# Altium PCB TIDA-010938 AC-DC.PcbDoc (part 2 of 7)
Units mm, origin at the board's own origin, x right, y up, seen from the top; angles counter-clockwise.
Board outline 275 x 170 mm, 4 copper layers (Top Layer, Layer 1, Layer 2, Bottom Layer), stack 1.787 mm thick; 711 components, 426 nets, 2196 pads, 1444 vias.
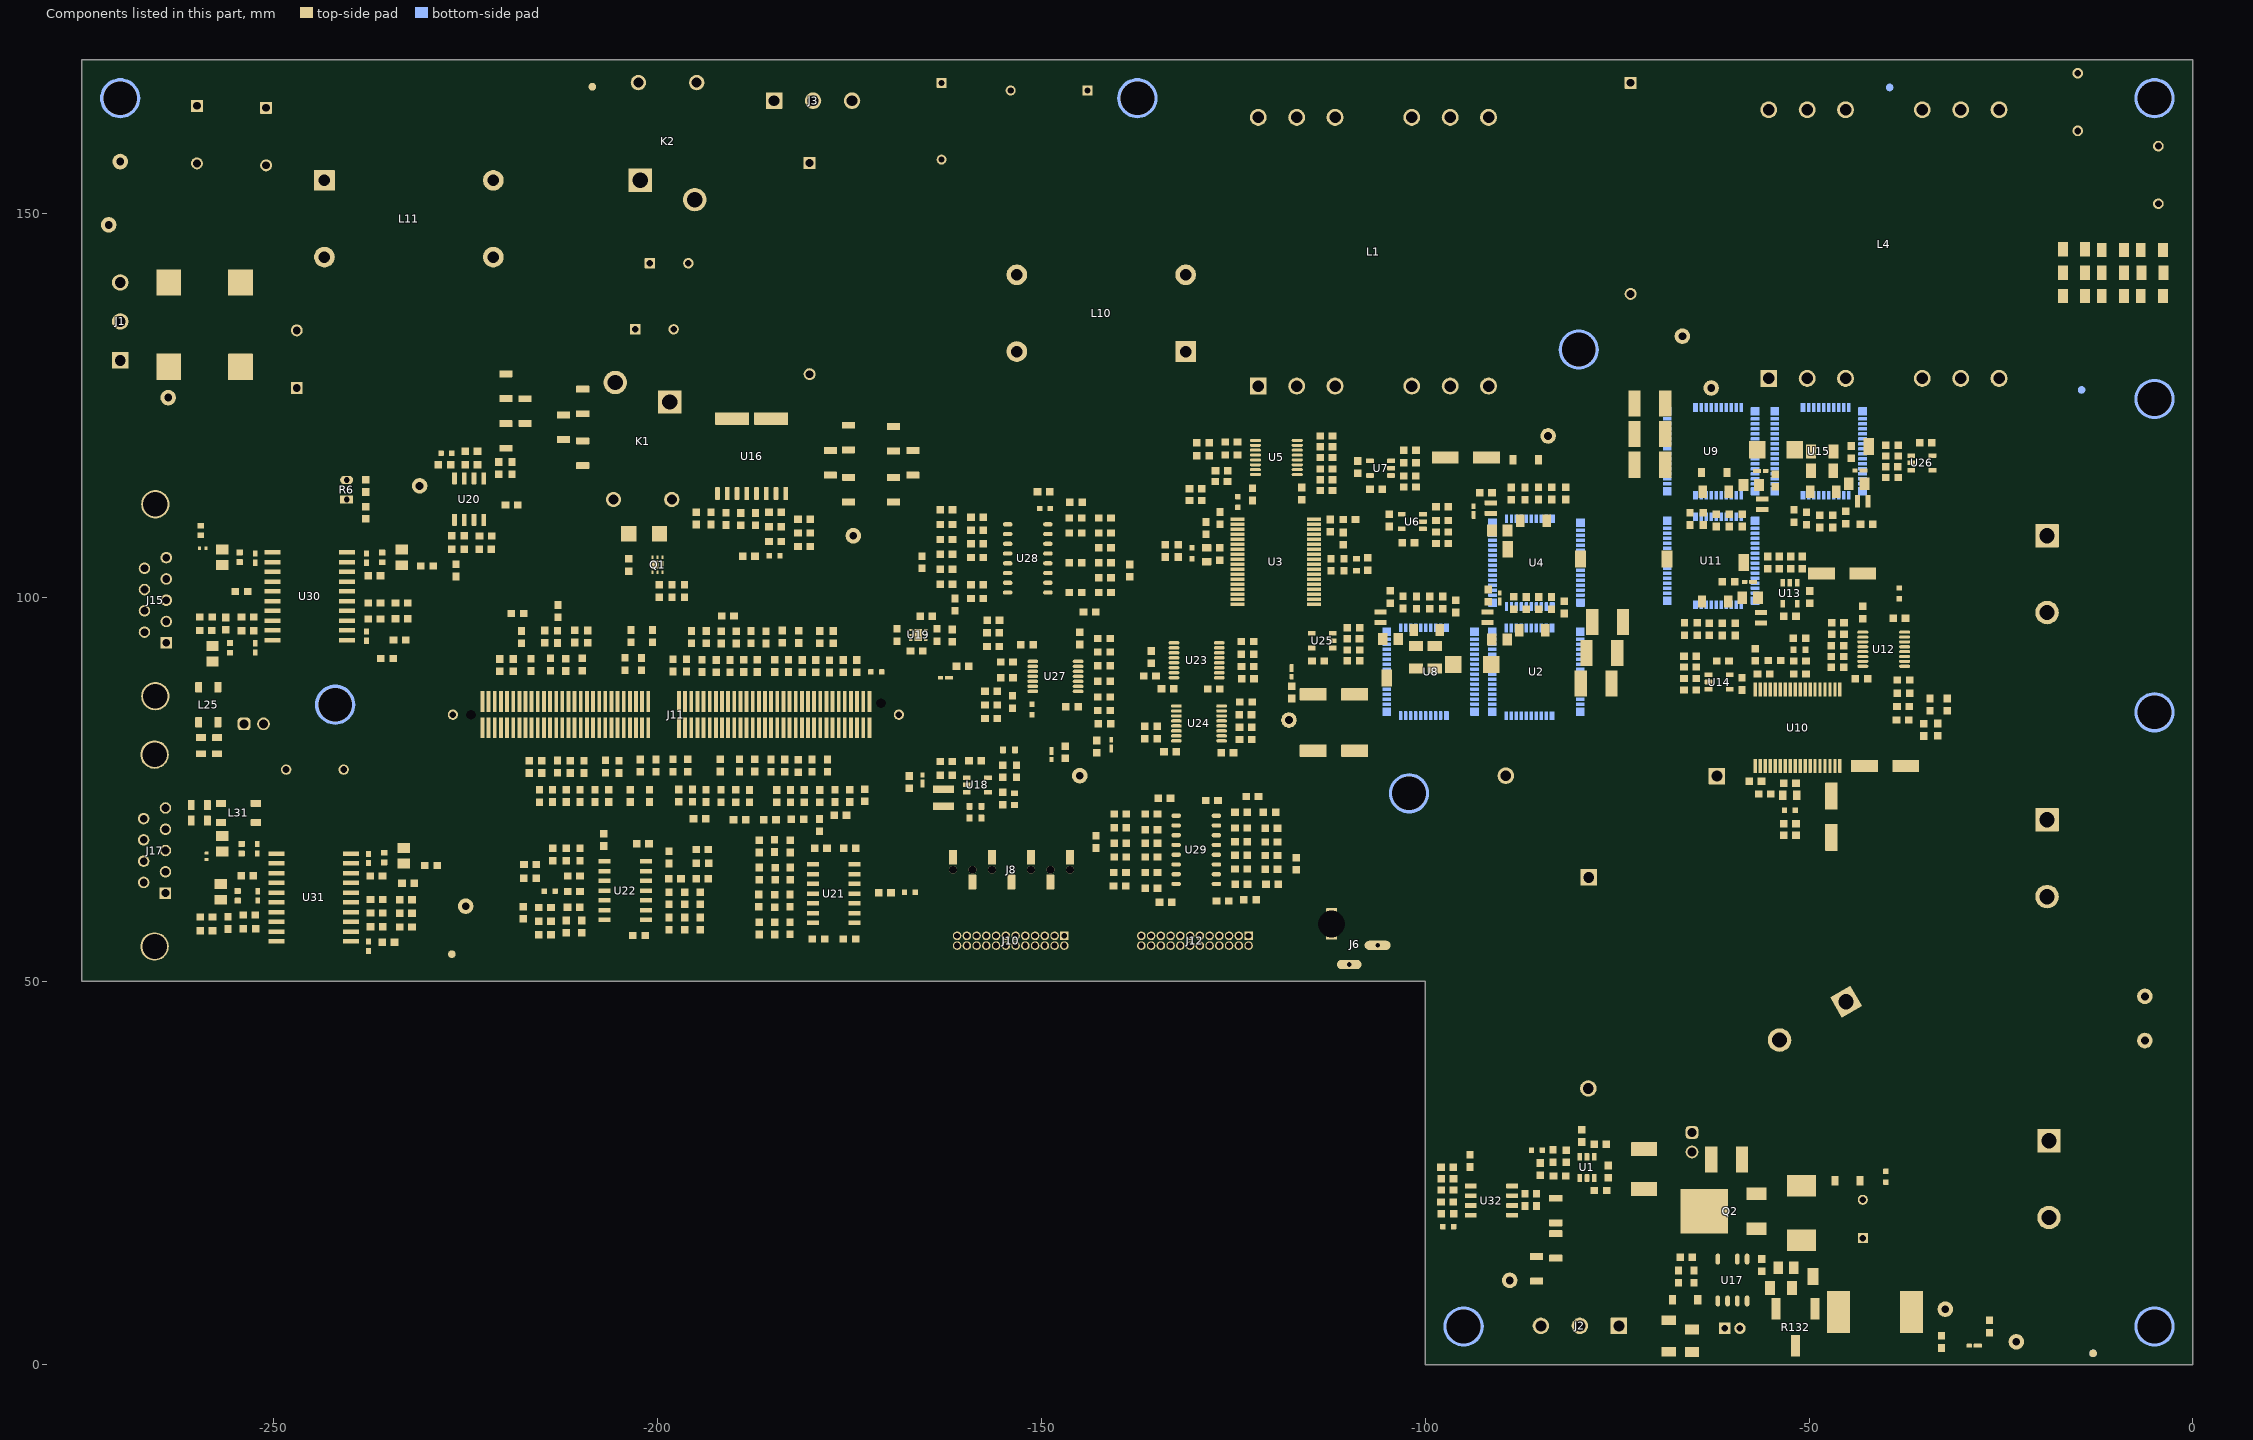
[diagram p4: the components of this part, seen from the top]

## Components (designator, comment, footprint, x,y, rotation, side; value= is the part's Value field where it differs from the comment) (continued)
R127 "TNPV12061M00BEEN" TNPV1206 -169.25,120.65 r270 top value=1.00Meg
R128 "TNPV12061M00BEEN" TNPV1206 -166.75,117.5 r270 top value=1.00Meg
R129 "TNPV12061M00BEEN" TNPV1206 -169.275,114 r270 top value=1.00Meg
R130 "RG1608P-103-B-T5" 0603 -224.25,117.25 r0 top value=10.0k
R131 "RG1608P-103-B-T5" 0603 -226,108 r0 top value=10.0k
R132 "3269W-1-104LF" FP-3269W-1-104LF_SMD-MFG -51.75,4.9 r180 top
R133 "RG1608P-103-B-T5" 0603 -97.15,25.75 r0 top value=10.0k
R134 "RG1608P-560-B-T5" 0603 -97.15,21.225 r180 top value=56
R135 "RG1608P-103-B-T5" 0603 -97.125,24.25 r180 top value=10.0k
R136 "RT0603BRD077K32L" 0603 -216.625,63.4 r180 top value=7.32k
R139 "RT0603BRD077K32L" 0603 -216.597,65.173 r0 top value=7.32k
R140 "RG1608P-560-B-T5" 0603 -175.001,55.474 r180 top value=56
R141 "RG1608P-560-B-T5" 0603 -206.998,68.379 r90 top value=56
R143 "RT0603BRD077K32L" 0603 -213.657,66.476 r270 top value=7.32k
R145 "RT0603BRD077K32L" 0603 -211.879,66.476 r270 top value=7.32k
R147 "RG1608P-103-B-T5" 0603 -214.673,59.576 r180 top value=10.0k
R149 "RG1608P-103-B-T5" 0603 -217.5,58.894 r270 top value=10.0k
R150 "RG1608P-560-B-T5" 0603 -174.968,67.302 r180 top value=56
R151 "RG1608P-560-B-T5" 0603 -214.673,56.02 r180 top value=56
R153 "RG1608P-103-B-T5" 0603 -214.673,57.798 r180 top value=10.0k
R155 "RG1608P-103-B-T5" 0603 -211.912,57.078 r270 top value=10.0k
R156 "RT0603BRD077K32L" 0603 -196.467,60.78 r90 top value=7.32k
R157 "RG1608P-103-B-T5" 0603 -184.675,63.975 r270 top value=10.0k
R158 "RG1608P-103-B-T5" 0603 -186.769,63.981 r90 top value=10.0k
R159 "RT0603BRD077K32L" 0603 -194.435,60.78 r270 top value=7.32k
R160 "RG1608P-560-B-T5" 0603 -178.74,67.3 r0 top value=56
R161 "RG1608P-560-B-T5" 0603 -202.426,55.933 r180 top value=56
R162 "RG1608P-103-B-T5" 0603 -186.769,67.537 r90 top value=10.0k
R163 "RT0603BRD077K32L" 0603 -194.435,57.478 r90 top value=7.32k
R164 "RG1608P-103-B-T5" 0603 -184.775,67.6 r90 top value=10.0k
R165 "RT0603BRD077K32L" 0603 -196.467,57.478 r90 top value=7.32k
R166 "RG1608P-103-B-T5" 0603 -194.143,65.352 r180 top value=10.0k
R167 "RG1608P-103-B-T5" 0603 -184.725,60.425 r270 top value=10.0k
R168 "RG1608P-103-B-T5" 0603 -186.802,60.467 r90 top value=10.0k
R169 "RG1608P-560-B-T5" 0603 -179.032,55.472 r0 top value=56
R170 "RG1608P-560-B-T5" 0603 -198.499,66.114 r90 top value=56
R171 "RG1608P-103-B-T5" 0603 -186.769,56.869 r270 top value=10.0k
R172 "RG1608P-103-B-T5" 0603 -194.181,63.32 r0 top value=10.0k
R173 "RG1608P-103-B-T5" 0603 -184.737,56.869 r270 top value=10.0k
R174 "RCS06030000Z0EA" 0603 -218.787,91.139 r90 top value=0
R175 "RCS06030000Z0EA" 0603 -217.738,94.798 r90 top value=0
R176 "RCS06030000Z0EA" 0603 -210.8,94.9 r270 top value=0
R177 "RCS06030000Z0EA" 0603 -123.15,94.225 r180 top value=0
R178 "RCS06030000Z0EA" 0603 -211.975,91.175 r270 top value=0
R179 "RCS06030000Z0EA" 0603 -216.501,91.177 r90 top value=0
R180 "RCS06030000Z0EA" 0603 -213.025,94.825 r270 top value=0
R181 "RCS06030000Z0EA" 0603 -213.95,91.225 r270 top value=0
R182 "RCS06030000Z0EA" 0603 -215.375,74.1 r270 top value=0
R183 "RCS06030000Z0EA" 0603 -215.075,77.9 r270 top value=0
R184 "RCS06030000Z0EA" 0603 -213.025,77.925 r270 top value=0
R185 "ERJ-8ENF1693V" 1206 -10.423,145.226 r0 top value=169k
R186 "RCS06030000Z0EA" 0603 -210.118,74.129 r90 top value=0
R187 "RCS06030000Z0EA" 0603 -209.585,77.901 r90 top value=0
R188 "RCS06030000Z0EA" 0603 -208.153,74.116 r90 top value=0
R189 "RCS06030000Z0EA" 0603 -206.791,77.939 r90 top value=0
R190 "RCS06030000Z0EA" 0603 -203.55,74.125 r90 top value=0
R191 "RCS06030000Z0EA" 0603 -202.1,91.275 r90 top value=0
R192 "RCS06030000Z0EA" 0603 -202.244,78.051 r90 top value=0
R193 "RCS06030000Z0EA" 0603 -200.65,94.925 r90 top value=0
R194 "RCS06030000Z0EA" 0603 -204.25,91.3 r270 top value=0
R195 "RCS06030000Z0EA" 0603 -196.05,78.075 r270 top value=0
R196 "RCS06030000Z0EA" 0603 -203.45,94.925 r270 top value=0
R197 "RCS06030000Z0EA" 0603 -195.45,74.15 r270 top value=0
R198 "RCS06030000Z0EA" 0603 -201.05,74.125 r90 top value=0
R199 "RCS06030000Z0EA" 0603 -200.2,78.05 r90 top value=0
R200 "RCS06030000Z0EA" 0603 -198,78.075 r90 top value=0
R201 "RCS06030000Z0EA" 0603 -197.225,74.15 r90 top value=0
R202 "RCS06030000Z0EA" 0603 -123.35,86.35 r180 top value=0
R203 "RCS06030000Z0EA" 0603 -193.69,74.125 r90 top value=0
R204 "RCS06030000Z0EA" 0603 -196.219,91.126 r90 top value=0
R205 "RCS06030000Z0EA" 0603 -191.83,78.089 r90 top value=0
R206 "RCS06030000Z0EA" 0603 -193.641,94.798 r90 top value=0
R207 "RCS06030000Z0EA" 0603 -192.338,91.026 r90 top value=0
R208 "RCS06030000Z0EA" 0603 -191.699,94.776 r90 top value=0
R209 "RCS06030000Z0EA" 0603 -190.56,91.026 r90 top value=0
R210 "RCS06030000Z0EA" 0603 -189.325,78.1 r90 top value=0
R211 "RCS06030000Z0EA" 0603 -189.758,94.776 r90 top value=0
R212 "RCS06030000Z0EA" 0603 -188.02,74.091 r90 top value=0
R213 "RCS06030000Z0EA" 0603 -188.782,91.064 r90 top value=0
R214 "RCS06030000Z0EA" 0603 -187.325,78.1 r90 top value=0
R215 "RCS06030000Z0EA" 0603 -187.816,94.798 r90 top value=0
R216 "RCS06030000Z0EA" 0603 -187.004,91.064 r90 top value=0
R217 "RCS06030000Z0EA" 0603 -185.226,78.051 r90 top value=0
R218 "RCS06030000Z0EA" 0603 -185.875,94.775 r90 top value=0
R219 "RCS06030000Z0EA" 0603 -184.464,74.091 r90 top value=0
R220 "RCS06030000Z0EA" 0603 -184.718,91.064 r90 top value=0
R221 "RCS06030000Z0EA" 0603 -183.448,78.051 r90 top value=0
R222 "RCS06030000Z0EA" 0603 -183.75,94.85 r90 top value=0
R223 "RCS06030000Z0EA" 0603 -182.686,74.091 r90 top value=0
R224 "RCS06030000Z0EA" 0603 -182.94,91.064 r90 top value=0
R225 "RCS06030000Z0EA" 0603 -181.67,78.013 r90 top value=0
R226 "RCS06030000Z0EA" 0603 -181.609,94.825 r90 top value=0
R227 "RCS06030000Z0EA" 0603 -180.908,74.091 r90 top value=0
R228 "RCS06030000Z0EA" 0603 -181.162,91.026 r90 top value=0
R229 "RCS06030000Z0EA" 0603 -179.892,78.051 r90 top value=0
R230 "RCS06030000Z0EA" 0603 -179.384,91.026 r90 top value=0
R231 "RCS06030000Z0EA" 0603 -178.876,74.091 r90 top value=0
R232 "RCS06030000Z0EA" 0603 -178.876,94.798 r90 top value=0
R233 "RCS06030000Z0EA" 0603 -177.86,78.051 r90 top value=0
R234 "RCS06030000Z0EA" 0603 -177.606,90.988 r90 top value=0
R235 "ERJ-8ENF1693V" 1206 -10.423,142.273 r0 top value=169k
R236 "RCS06030000Z0EA" 0603 -177.098,94.798 r90 top value=0
R237 "RG1608P-103-B-T5" 0603 -97.8,107 r180 top value=10.0k
R238 "RG1608P-560-B-T5" 0603 -156.541,84.189 r0 top value=56
R239 "RG1608P-560-B-T5" 0603 -154.509,89.523 r180 top value=56
R240 "RCS06030000Z0EA" 0603 -122.525,74.025 r180 top value=0
R241 "RCS06030000Z0EA" 0603 -145.5,112.375 r180 top value=0
R242 "RCS06030000Z0EA" 0603 -116.8,65.275 r270 top value=0
R243 "RCS06030000Z0EA" 0603 -138.475,103.45 r270 top value=0
R244 "RCS06030000Z0EA" 0603 -122.827,60.598 r180 top value=0
R245 "RCS06030000Z0EA" 0603 -143.725,98.075 r180 top value=0
R246 "RCS06030000Z0EA" 0603 -133.825,60.25 r180 top value=0
R247 "RCS06030000Z0EA" 0603 -161.25,99.025 r270 top value=0
R248 "RCS06030000Z0EA" 0603 -142.9,68.125 r270 top value=0
R249 "RCS06030000Z0EA" 0603 -165.55,104.55 r270 top value=0
R250 "RCS06030000Z0EA" 0603 -133.975,73.825 r0 top value=0
R251 "RCS06030000Z0EA" 0603 -158.375,110.425 r180 top value=0
R252 "RG1608P-103-B-T5" 0603 -141.846,87.008 r180 top value=10.0k
R253 "RG1608P-103-B-T5" 0603 -123.983,72.001 r180 top value=10.0k
R254 "RG1608P-103-B-T5" 0603 -145.553,110.312 r180 top value=10.0k
R255 "RG1608P-103-B-T5" 0603 -141.846,91.072 r180 top value=10.0k
R256 "RG1608P-103-B-T5" 0603 -154.509,91.555 r0 top value=10.0k
R257 "RG1608P-560-B-T5" 0603 -158.375,106.947 r180 top value=56
R258 "RG1608P-103-B-T5" 0603 -156.541,87.745 r0 top value=10.0k
R259 "RG1608P-560-B-T5" 0603 -135.667,69.715 r180 top value=56
R260 "RG1608P-560-B-T5" 0603 -162.385,109.463 r0 top value=56
R263 "RG1608P-560-B-T5" 0603 -139.731,71.747 r0 top value=56
R264 "RG1608P-560-B-T5" 0603 -135.667,66.159 r180 top value=56
R265 "RG1608P-560-B-T5" 0603 -162.385,105.58 r0 top value=56
R267 "RG1608P-560-B-T5" 0603 -139.731,67.937 r0 top value=56
R268 "RG1608P-560-B-T5" 0603 -162.385,101.697 r0 top value=56
R269 "RG1608P-560-B-T5" 0603 -158.375,99.835 r180 top value=56
R270 "RG1608P-560-B-T5" 0603 -139.769,64.127 r0 top value=56
R272 "RG1608P-560-B-T5" 0603 -135.667,62.095 r180 top value=56
R273 "RG1608P-560-B-T5" 0603 -141.743,100.602 r180 top value=56
R274 "RG1608P-560-B-T5" 0603 -119.935,62.603 r180 top value=56
R276 "RG1608P-560-B-T5" 0603 -141.743,104.485 r180 top value=56
R278 "RG1608P-560-B-T5" 0603 -120.049,66.344 r180 top value=56
R279 "RG1608P-560-B-T5" 0603 -126.4,60.425 r0 top value=56
R280 "RT0603DRE0759R7L" 0603 -253.41,95.645 r0 top value=59.7
R281 "RG1608P-560-B-T5" 0603 -141.743,108.368 r180 top value=56
R282 "RG1608P-560-B-T5" 0603 -120.049,69.9 r180 top value=56
R284 "RG1608P-560-B-T5" 0603 -123.983,64.602 r0 top value=56
R286 "RG1608P-560-B-T5" 0603 -123.983,68.158 r0 top value=56
R287 "RT0603DRE0759R7L" 0603 -253.41,97.423 r180 top value=59.7
R288 "RT0603DRE0759R7L" 0603 -253.152,56.82 r0 top value=59.7
R289 "RT0603DRE0759R7L" 0603 -253.19,58.598 r180 top value=59.7
R290 "ERJ-8ENF1693V" 1206 -10.423,139.225 r0 top value=169k
R291 "ERJ-8ENF1693V" 1206 -15.503,139.225 r0 top value=169k
R297 "RG1608P-103-B-T5" 0603 -141.743,110.31 r180 top value=10.0k
R298 "RG1608P-103-B-T5" 0603 -141.743,106.427 r180 top value=10.0k
R299 "RG1608P-103-B-T5" 0603 -141.743,102.544 r180 top value=10.0k
R300 "RG1608P-103-B-T5" 0603 -162.385,103.639 r0 top value=10.0k
R301 "RG1608P-103-B-T5" 0603 -162.385,107.522 r0 top value=10.0k
R302 "RG1608P-103-B-T5" 0603 -162.385,111.405 r0 top value=10.0k
R303 "RG1608P-103-B-T5" 0603 -120.289,72.001 r180 top value=10.0k
R304 "RG1608P-103-B-T5" 0603 -120.049,68.122 r180 top value=10.0k
R305 "RG1608P-103-B-T5" 0603 -120.049,64.566 r180 top value=10.0k
R306 "RG1608P-103-B-T5" 0603 -139.807,62.386 r0 top value=10.0k
R307 "RG1608P-103-B-T5" 0603 -139.731,66.159 r0 top value=10.0k
R308 "RG1608P-103-B-T5" 0603 -139.731,69.969 r0 top value=10.0k
R310 "RG1608P-103-B-T5" 0603 -236.9,102.794 r0 top value=10.0k
R311 "RG1608P-560-B-T5" 0603 -233.344,97.206 r180 top value=56
R312 "RMCF0805ZT0R00" FP-RMCF0805ZT0R00_0805-MFG -257.375,80.65 r270 top
R314 "RG1608P-560-B-T5" 0603 -233.344,99.238 r180 top value=56
R316 "RMCF0805ZT0R00" FP-RMCF0805ZT0R00_0805-MFG -259.475,80.65 r270 top
R318 "RG1608P-103-B-T5" 0603 -236.642,63.678 r0 top value=10.0k
R319 "RG1608P-560-B-T5" 0603 -236.604,58.852 r180 top value=56
R320 "RG1608P-560-B-T5" 0603 -236.604,60.63 r180 top value=56
R321 "RMCF0805ZT0R00" FP-RMCF0805ZT0R00_0805-MFG -259.7,70.9 r180 top
R323 "RG1608P-560-B-T5" 0603 -236.604,57.074 r180 top value=56
R325 "RMCF0805ZT0R00" FP-RMCF0805ZT0R00_0805-MFG -259.7,72.9 r180 top
R326 "ERJ-8ENF1693V" 1206 -15.503,145.321 r0 top value=169k
R327 "ERJ-8ENF1693V" 1206 -15.503,142.273 r0 top value=169k
R328 "RG1608P-103-B-T5" 0603 -97.8,111.8 r180 top value=10.0k
R329 "RG1608P-103-B-T5" 0603 -102,114.35 r180 top value=10.0k
R330 "RG1608P-103-B-T5" 0603 -102,119.125 r180 top value=10.0k
R331 "RG1608P-103-B-T5" 0603 -50.9,104.5 r270 top value=10.0k
R332 "RG1608P-103-B-T5" 0603 -55.4,104.5 r270 top value=10.0k
R335 "RG1608P-103-B-T5" 0603 -109.35,91.725 r180 top value=10.0k
R336 "RG1608P-103-B-T5" 0603 -39.2,119.8 r0 top value=10.0k
R337 "RG1608P-103-B-T5" 0603 -109.35,96.025 r180 top value=10.0k
R338 "RG1608P-103-B-T5" 0603 -39.2,115.6 r0 top value=10.0k
TP1 "S2751-46R" Harwin_S2751-46R -68.5,105 r90 top
TP2 "5001" Keystone5001 -225,59.75 r90 top
TP3 "5001" Keystone5001 -174.5,108 r90 top
TP4 "5001" Keystone5001 -84,121 r90 top
TP5 "S2751-46R" Harwin_S2751-46R -79.775,104.952 r90 top
TP6 "5001" Keystone5001 -231,114.5 r90 top
TP7 "5000" Keystone5000 -89,11 r90 top
TP8 "5001" Keystone5001 -6.25,42.25 r90 top
TP9 "5001" Keystone5001 -66.5,134 r90 top
TP10 "5001" Keystone5001 -62.75,127.25 r90 top
TP11 "S2751-46R" Harwin_S2751-46R -42.234,119.65 r90 top
TP12 "5001" Keystone5001 -117.75,84 r90 top
TP13 "5001" Keystone5001 -271.5,148.5 r90 top
TP14 "5116" Keystone_5116 -270,156.75 r0 top
TP15 "5117" Keystone5117 -263.75,126 r90 top
TP16 "S2751-46R" Harwin_S2751-46R -105.018,89.452 r90 top
TP17 "S2751-46R" Harwin_S2751-46R -89.25,106.25 r270 top
TP18 "S2751-46R" Harwin_S2751-46R -58.5,104.5 r90 top
TP19 "5000" Keystone5000 -6.25,48 r90 top
TP20 "5000" Keystone5000 -32.25,7.25 r90 top
TP21 "5001" Keystone5001 -23,3 r90 top
TP22 "5001" Keystone5001 -145,76.75 r90 top
TP23 "S2751-46R" Harwin_S2751-46R -49.5,11.5 r90 top
U1 "INA181A3IDBV" DBV0006A_N -78.933,25.718 r90 top
U2 "LMG3522R030-Q1" RQS0052C-C01-MFG -85.535,90.275 r180 bottom
U3 "UCC14131QDWNRQ1" DWJ0036A-MFG -119.475,104.625 r0 top
U4 "LMG3522R030-Q1" RQS0052C-C01-MFG -85.5,104.5 r180 bottom
U5 "ISO7762DBQR" DBQ0016A_N -119.4,118.2 r180 top
U6 "SN74LVC1G08DBVT" DBV0005A_N -101.675,109.85 r180 top
U7 "SN74LVC1G08DBVT" DBV0005A_N -105.825,116.8 r180 top
U8 "LMG3522R030-Q1" RQS0052C-C01-MFG -99.293,90.3 r180 bottom
U9 "LMG3522R030-Q1" RQS0052C-C01-MFG -62.75,119 r0 bottom
U10 "UCC14131QDWNRQ1" DWJ0036A-MFG -51.5,83 r90 top
U11 "LMG3522R030-Q1" RQS0052C-C01-MFG -62.75,104.75 r0 bottom
U12 "ISO7762DBQR" DBQ0016A_N -40.275,93.223 r0 top
U13 "SN74LVC1G08DBVT" DBV0005A_N -52.5,100.5 r270 top
U14 "SN74LVC1G08DBVT" DBV0005A_N -61.725,88.95 r0 top
U15 "LMG3522R030-Q1" RQS0052C-C01-MFG -48.75,119 r0 bottom
U16 "TMCS1123B2QDVGR" DVG0010A-MFG -187.75,118.391 r270 top
U17 "UCC28710DR" D0007A_N -59.984,11.052 r90 top
U18 "TPS560200DBVR" DBV0005A_N -158.333,75.549 r0 top
U19 "TLV75533PDRVR" DRV0006A -166.06,95.076 r0 top
U20 "OPA2388IDR" D0008A-MFG -224.55,112.775 r90 top
U21 "OPA4388IDR" D0014A-MFG -177.047,61.387 r180 top
U22 "OPA4388IDR" D0014A-MFG -204.204,61.775 r0 top
U23 "SN74HC251PW" PW0016A_N -129.775,91.775 r180 top
U24 "SN74HC251PW" PW0016A_N -129.475,83.55 r180 top
U25 "SN74LVC1G08DBVT" DBV0005A_N -113.426,94.329 r180 top
U26 "SN74LVC1G08DBVT" DBV0005A_N -35.3,117.5 r0 top
U27 "SN74LVC126APWR" PW0014A_N -148.169,89.683 r180 top
U28 "SN74HC365D" D0016A_L -151.775,105.05 r0 top
U29 "SN74HC365D" D0016A_L -129.825,67.09 r0 top
U30 "ISOW1044DFM" DFM0020A-MFG -245.306,100.127 r180 top
U31 "ISOW1412DFM" DFM0020A-MFG -244.77,60.884 r180 top
U32 "OPA2388IDR" D0008A-MFG -91.375,21.4 r180 top
ZZ1 "This Assembly Note is for PCB labels only" AssemblyNoteLabel -281.335,-76 r0 top
ZZ2 "These assemblies are ESD sensitive, ESD precautions shall be observed." AssemblyNote -218.585,-72.25 r0 top
ZZ3 "These assemblies must be clean and free from flux and all contaminants. Use of no clean flux is not acceptable." AssemblyNote 1.964,5.922 r90 top
ZZ4 "These assemblies must comply with workmanship standards IPC-A-610 Class 2, unless otherwise specified." AssemblyNote -249.835,-64.75 r0 top

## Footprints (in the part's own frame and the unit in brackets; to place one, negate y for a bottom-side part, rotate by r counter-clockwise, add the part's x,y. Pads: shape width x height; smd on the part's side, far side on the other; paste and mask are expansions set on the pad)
0402 [mm] "0402 from SM-752 data"
  rect 0.8x0.6 smd: 1(-0.6,0) 2(0.6,0)
  silkscreen extent -1.22,-0.52 1.22,0.52, body extent -0.55,-0.3 0.55,0.3, height 0.6
0603 [mm] "0603 from SM-752 data"
  rect 1x0.95 smd: 1(-0.8,0) 2(0.8,0)
  silkscreen extent -1.52,-0.69 1.52,0.69, body extent -0.87,-0.47 0.87,0.47, height 1
0704 [mm] "Murata"
  rrect11% 1x1.2 smd: 1(-0.9,0) 2(0.9,0)
  silkscreen extent -0.25,-0.77 0.25,0.8, body extent -0.95,-0.55 0.95,0.55, height 0.8
0805_HV [mil] "0805 with 30mil clearance between pads"
  rect 50x63 smd: 1(-40,0) 2(40,0)
  silkscreen extent -74,-40 74,40, body extent -43,-29 43,29, height 57
1206 [mm] "1206 from SM-752 data"
  rect 1.3x1.85 smd: 1(-1.45,0) 2(1.45,0)
  silkscreen extent -2.4,-1.21 2.4,1.21, body extent -1.7,-0.9 1.7,0.9, height 1.35
1206_180 [mm] "1206_180"
  rect 1.1x1.6 smd: 1(-1.7,0) 2(1.7,0)
  silkscreen extent -0.9,-1 0.9,1, body extent -1.75,-0.95 1.75,0.95, height 1.8
1812_254 [mm] "SMD, 2-Leads, Body 4.8x3.4mm"
  rect 1.6x3.4 smd: 1(-2,0) 2(2,0)
  silkscreen extent -0.8,-1.7 0.8,1.7, body extent -2.4,-1.7 2.4,1.7, height 2.54
AssemblyNote [mm] "Assembly Note"
AssemblyNoteLabel [mm] "Assembly Note for PCB Labels"
CAPPR2-5x11 [mm] "Capacitor, Electrolytic, Radial; Body 5 x 11 mm (Dia.xH typ); Pin Spacing 2 mm (typ)"
  rrect7% 1.5x1.5 hole 0.85: 1(-1,0)
  round 1.5 hole 0.85: 2(1,0)
  silkscreen extent -2.5,-2.5 2.5,2.5, body extent -2.53,-2.53 2.53,2.52, height 11.29
CE_Mark_5mm [mm] "Minimum text height for CE Mark"
  silkscreen extent -3.5,-2.5 3.5,2.5
CK45_1250x600x1650 [mm] "TH, 2-Leads, Dia 12.5mm, Pin Spacing 7.5mm"
  round 1.35 hole 0.9: 1(-3.75,0) 2(3.75,0)
  body extent -6.25,-3 6.25,3, height 16.25
controlCARD-120HSEC [mm] "Pads are not numbered according to Samtec datasheet."
  rect 0.5x2.724 smd: 1(-23.357,-1.678) 2(-23.357,1.722) 3(-22.557,-1.678) 4(-22.557,1.722) 5(-21.757,-1.678) 6(-21.757,1.722) 7(-20.957,-1.678) 8(-20.957,1.722) 9(-20.157,-1.678) 10(-20.157,1.722) 11(-19.357,-1.678) 12(-19.357,1.722) 13(-18.557,-1.678) 14(-18.557,1.722) 15(-17.757,-1.678) 16(-17.757,1.722) 17(-16.957,-1.678) 18(-16.957,1.722) 19(-16.157,-1.678) 20(-16.157,1.722) 21(-15.357,-1.678) 22(-15.357,1.722) 23(-14.557,-1.678) 24(-14.557,1.722) 25(-13.757,-1.678) 26(-13.757,1.722) 27(-12.957,-1.678) 28(-12.957,1.722) 29(-12.157,-1.678) 30(-12.157,1.722) 31(-11.357,-1.678) 32(-11.357,1.722) 33(-10.557,-1.678) 34(-10.557,1.722) 35(-9.757,-1.678) 36(-9.757,1.722) 37(-8.957,-1.678) 38(-8.957,1.722) 39(-8.157,-1.678) 40(-8.157,1.722) 41(-7.357,-1.678) 42(-7.357,1.722) 43(-6.557,-1.678) 44(-6.557,1.722) 45(-5.757,-1.678) 46(-5.757,1.722) 47(-4.957,-1.678) 48(-4.957,1.722) 49(-4.157,-1.678) 50(-4.157,1.722) 51(-3.357,-1.678) 52(-3.357,1.722) 53(-2.557,-1.678) 54(-2.557,1.722) 55(-1.757,-1.678) 56(-1.757,1.722) 57(2.243,-1.678) 58(2.243,1.722) 59(3.043,-1.678) 60(3.043,1.722) 61(3.843,-1.678) 62(3.843,1.722) 63(4.643,-1.678) 64(4.643,1.722) 65(5.443,-1.678) 66(5.443,1.722) 67(6.243,-1.678) 68(6.243,1.722) 69(7.043,-1.678) 70(7.043,1.722) 71(7.843,-1.678) 72(7.843,1.722) 73(8.643,-1.678) 74(8.643,1.722) 75(9.443,-1.678) 76(9.443,1.722) 77(10.243,-1.678) 78(10.243,1.722) 79(11.043,-1.678) 80(11.043,1.722) 81(11.843,-1.678) 82(11.843,1.722) 83(12.643,-1.678) 84(12.643,1.722) 85(13.443,-1.678) 86(13.443,1.722) 87(14.243,-1.678) 88(14.243,1.722) 89(15.043,-1.678) 90(15.043,1.722) 91(15.843,-1.678) 92(15.843,1.722) 93(16.643,-1.678) 94(16.643,1.722) 95(17.443,-1.678) 96(17.443,1.722) 97(18.243,-1.678) 98(18.243,1.722) 99(19.043,-1.678) 100(19.043,1.722) 101(19.843,-1.678) 102(19.843,1.722) 103(20.643,-1.678) 104(20.643,1.722) 105(21.443,-1.678) 106(21.443,1.722) 107(22.243,-1.678) 108(22.243,1.722) 109(23.043,-1.678) 110(23.043,1.722) 111(23.843,-1.678) 112(23.843,1.722) 113(24.643,-1.678) 114(24.643,1.722) 115(25.443,-1.678) 116(25.443,1.722) 117(26.243,-1.678) 118(26.243,1.722) 119(27.043,-1.678) 120(27.043,1.722)
  round 0.025 hole 1.27 unplated mask+0.876: 181(-24.857,0.022) 182(28.543,1.522)
  round 1.348 hole 0.84: 185(-27.207,0.022) 186(30.893,0.022)
  silkscreen extent -32.11,-3.86 35.8,3.9, body extent -31.75,-3.48 35.3,3.52, height 12.35
CSS2H-2512_H077Y042 [mm] "SMD, 2-Leads, Body 6.35x3.05mm"
  rrect6% 1.8x3.4 smd: 1(-2.6,0) 2(2.6,0)
  body extent -3.18,-1.52 3.17,1.53, height 0.83
D0007A_N [mm] "SOIC, 7-Leads, Body 4.9x3.9mm, Pitch 1.27mm, IPC Medium Density"
  oval 1.45x0.6 smd: 1(-2.725,1.905) 2(-2.725,0.635) 3(-2.725,-0.635) 4(-2.725,-1.905) 5(2.725,-1.905) 6(2.725,-0.635) 8(2.725,1.905)
  silkscreen extent -3.32,-2.5 1.1,2.52, body extent -3.01,-2.45 3.01,2.45, height 1.75
D0008A-MFG [mm]
  rrect17% 1.55x0.6 smd paste+0 mask+0: 1(-2.7,1.905) 2(-2.7,0.635) 3(-2.7,-0.635) 4(-2.7,-1.905) 5(2.7,-1.905) 6(2.7,-0.635) 7(2.7,0.635) 8(2.7,1.905)
  silkscreen extent -4.17,-2.5 1.5,2.5, body extent -3.57,-2.75 3.57,2.75, height 0.25
D0014A-MFG [mm]
  rrect17% 1.55x0.6 smd paste-1000 mask+0: 1(-2.7,3.81) 2(-2.7,2.54) 3(-2.7,1.27) 4(-2.7,0) 5(-2.7,-1.27) 6(-2.7,-2.54) 7(-2.7,-3.81) 8(2.7,-3.81) 9(2.7,-2.54) 10(2.7,-1.27) 11(2.7,0) 12(2.7,1.27) 13(2.7,2.54) 14(2.7,3.81)
  silkscreen extent -4.15,-4.38 1.55,4.38, body extent -3.57,-4.62 3.57,4.62, height 0.25
D0016A_L [mm] "SOIC, 16-Leads, Body 9.9x3.9mm, Pitch 1.27mm, IPC High Density"
  oval 1.25x0.55 smd: 1(-2.625,4.445) 2(-2.625,3.175) 3(-2.625,1.905) 4(-2.625,0.635) 5(-2.625,-0.635) 6(-2.625,-1.905) 7(-2.625,-3.175) 8(-2.625,-4.445) 9(2.625,-4.445) 10(2.625,-3.175) 11(2.625,-1.905) 12(2.625,-0.635) 13(2.625,0.635) 14(2.625,1.905) 15(2.625,3.175) 16(2.625,4.445)
  silkscreen extent -3.1,-5 0.9,5, body extent -3,-4.95 3,4.95, height 1.6
DBQ0016A_N [mm] "SOP, 16-Leads, Body 4.9x3.9mm, Pitch 0.635mm, IPC Medium Density"
  oval 1.45x0.4 smd: 1(-2.725,2.222) 2(-2.725,1.587) 3(-2.725,0.952) 4(-2.725,0.317) 5(-2.725,-0.318) 6(-2.725,-0.953) 7(-2.725,-1.588) 8(-2.725,-2.223) 9(2.725,-2.222) 10(2.725,-1.587) 11(2.725,-0.952) 12(2.725,-0.317) 13(2.725,0.318) 14(2.725,0.953) 15(2.725,1.588) 16(2.725,2.223)
  silkscreen extent -3.35,-2.5 1.1,2.68, body extent -3.01,-2.45 3.01,2.45, height 1.63
DBV0005A_N [mm] "SOT23, 5-Leads, Body 2.9x1.6mm, Pitch 0.95mm, Lead Span 2.8mm, IPC Medium Density"
  rrect17% 1x0.6 smd: 1(-1.375,0.95) 2(-1.375,0) 3(-1.375,-0.95) 4(1.375,-0.95) 5(1.375,0.95)
  silkscreen extent -0.25,-1.55 0.25,1.55, body extent -1.42,-1.46 1.42,1.46, height 1.09
DBV0006A_N [mm] "SOT23, 6-Leads, Body 2.9x1.6mm, Pitch 0.95mm, Lead Span 2.8mm, IPC Medium Density"
  rrect17% 1x0.6 smd: 1(-1.375,0.95) 2(-1.375,0) 3(-1.375,-0.95) 4(1.375,-0.95) 5(1.375,0) 6(1.375,0.95)
  silkscreen extent -1.68,-1.55 0.5,1.55, body extent -1.42,-1.46 1.42,1.46, height 1.12
DFM0020A-MFG [mm]
  rrect17% 2.1x0.6 smd paste+0 mask+0: 1(-4.85,5.715) 2(-4.85,4.445) 3(-4.85,3.175) 4(-4.85,1.905) 5(-4.85,0.635) 6(-4.85,-0.635) 7(-4.85,-1.905) 8(-4.85,-3.175) 9(-4.85,-4.445) 10(-4.85,-5.715) 11(4.85,-5.715) 12(4.85,-4.445) 13(4.85,-3.175) 14(4.85,-1.905) 15(4.85,-0.635) 16(4.85,0.635) 17(4.85,1.905) 18(4.85,3.175) 19(4.85,4.445) 20(4.85,5.715)
  silkscreen extent -6.58,-6.47 3.4,6.47, body extent -6,-6.72 6,6.72, height 0.25
DPAK [mm] "D-PAK, 3-Pads, Body 6.22x6.73mm (max), TO-252AA using nominal STEP model"
  rrect6% 2.6x1.6 smd: 1(-3.4,2.28) 3(-3.4,-2.28)
  rrect2% 6.2x5.8 smd paste-3: 2(3.4,0)
  body extent -3.86,-3.29 5.84,3.29, height 2.48
DRV0006A [mm] "SON, 6-Leads, Body 2x2mm, Pitch 0.65mm, Thermal Pad 1.6x1mm, TI Recommended"
  rrect33% 0.45x0.3 smd: 1(-0.975,0.65) 2(-0.975,0) 3(-0.975,-0.65) 4(0.975,-0.65) 5(0.975,0) 6(0.975,0.65)
  rrect14% 1x0.7 on Top Paste: 7(0,-0.45) 7(0,0.45)
  rrect10% 1x1.6 smd paste-0.5: 7(0,0)
  silkscreen extent -1.05,-1.2 1.05,1.2, body extent -1.05,-1.05 1.05,1.05, height 0.81
DVG0010A-MFG [mm]
  rrect6% 1.65x4.41 smd paste+0 mask+0: 1(-4.875,2.54) 2(-4.875,-2.54)
  rrect17% 1.65x0.6 smd paste+0 mask+0: 3(4.875,-4.445) 4(4.875,-3.175) 5(4.875,-1.905) 6(4.875,-0.635) 7(4.875,0.635) 8(4.875,1.905) 9(4.875,3.175) 10(4.875,4.445)
  silkscreen extent -6.35,-5.25 3.8,5.25, body extent -5.8,-5.5 5.8,5.5, height 0.25
DWJ0036A-MFG [mm]
  rrect22% 1.85x0.45 smd paste+0 mask+0: 1(-4.975,5.525) 2(-4.975,4.875) 3(-4.975,4.225) 4(-4.975,3.575) 5(-4.975,2.925) 6(-4.975,2.275) 7(-4.975,1.625) 8(-4.975,0.975) 9(-4.975,0.325) 10(-4.975,-0.325) 11(-4.975,-0.975) 12(-4.975,-1.625) 13(-4.975,-2.275) 14(-4.975,-2.925) 15(-4.975,-3.575) 16(-4.975,-4.225) 17(-4.975,-4.875) 18(-4.975,-5.525) 19(4.975,-5.525) 20(4.975,-4.875) 21(4.975,-4.225) 22(4.975,-3.575) 23(4.975,-2.925) 24(4.975,-2.275) 25(4.975,-1.625) 26(4.975,-0.975) 27(4.975,-0.325) 28(4.975,0.325) 29(4.975,0.975) 30(4.975,1.625) 31(4.975,2.275) 32(4.975,2.925) 33(4.975,3.575) 34(4.975,4.225) 35(4.975,4.875) 36(4.975,5.525)
  silkscreen extent -6.57,-6.47 3.8,6.47, body extent -6,-6.72 6,6.72, height 0.25
E_900x700x900 [mm] "TH, 2- Leads, Body 9x7mm, Pin Spacing 7.5mm"
  round 1.4 hole 0.9: 1(-3.75,0) 2(3.75,0)
  silkscreen extent -4.5,-3.5 4.5,3.5, body extent -4.49,-3.5 4.49,3.5, height 11.96
FCC_disclaimer [mm]
Fiducial10-20 [mm]
  round 1 smd mask+0.5: 1(0,0)
  Top Layer keep-out circle w1.178: c0,0 r0.5
FP-3269W-1-104LF_SMD-MFG [mm]
  rrect8% 1.19x2.79 smd paste+0 mask+0: 1(-2.54,-2.415) 2(0,2.415) 3(2.54,-2.415)
  silkscreen extent -3.43,-2.28 3.43,2.28, body extent -3.53,-3.91 3.53,3.91, height 0.25
FP-796636-3_HDR3-MFG [mm]
  rrect5% 2.15x2.15 hole 1.4 paste-1000 mask+0: 1(-4.83,-0.325)
  round 2.15 hole 1.4 paste-1000 mask+0: 2(0.25,-0.325) 3(5.33,-0.325)
  silkscreen extent -8.78,-4.88 8.78,4.25, body extent -8.88,-4.35 8.88,4.35, height 0.25
FP-2071556-3_PTH_RELAY_18MM2_10MM2-MFG [mm]
  rrect3% 3.05x3.05 hole 2 paste-1000 mask+0: 1(-4.77,3.55)
  round 2 hole 1.3 paste-1000 mask+0: 2(7.93,3.8) 4(7.93,-3.8)
  round 3.05 hole 2 paste-1000 mask+0: 3(-7.31,-3.55)
  silkscreen extent -9.35,-5.35 9.35,6.03, body extent -9.45,-5.45 9.45,5.45, height 0.25
FP-9774015960R_ROUND_SPACER_6MM0-MFG [mm]
  round 5.245 smd paste-1000 mask-1000: 1(0,0)
  round 4.4 hole 4.4 unplated paste-1000 mask+0: ""(0,0)
  Top Layer circle w1.5: c0,0 r2.95
  silkscreen extent -4.15,-4.15 4.15,4.15, body extent -3,-3 3,3, height 1.6
FP-694106402002_CONN_PWR_10MM7_9MM0-MFG [mm]
  rrect7% 1.4x4.1 hole 3.5 slot 0.8 at 0 deg paste-1000 mask+0: 1(-3.5,1.15)
  rrect100% 3.2x1.2 hole 0.6 slot 2.6 at 0 deg paste-1000 mask+0: 2(-1.2,-4.15)
  rrect100% 3.4x1.2 hole 0.6 slot 2.8 at 0 deg paste-1000 mask+0: 3(2.5,-1.65)
  silkscreen extent -4.75,-5.5 4.75,5.5, body extent -4.85,-5.6 4.85,5.6, height 0.25
FP-ACT45B-101-2P-TL003_SMT_4MM5_3MM2-MFG [mm]
  rrect11% 1.35x0.9 smd paste+0 mask+0: 1(-2.275,1.25) 2(-2.275,-1.25) 3(2.275,-1.25) 4(2.275,1.25)
  silkscreen extent -3.62,-1.7 2.35,1.7, body extent -3.05,-1.8 3.05,1.8, height 0.25
FP-ALH82D161DD600_RADIAL-MFG [mm]
  rrect3% 3.05x3.05 hole 2 paste-1000 mask+0: 1(-5,0)
  round 3.05 hole 2 paste-1000 mask+0: 2(5,0)
  silkscreen extent -18,-18 18,18, body extent -18.1,-18.1 18.1,18.1, height 0.25
FP-B180990_PTH12_39MM8_41MM4-MFG [mm]
  rrect5% 2.2x2.2 hole 1.5 paste-1000 mask+0: 1(-17.5,15)
  round 2.2 hole 1.5 paste-1000 mask+0: 2(-17.5,10) 3(-17.5,5) 4(-17.5,-5) 5(-17.5,-10) 6(-17.5,-15) 7(17.5,-15) 8(17.5,-10) 9(17.5,-5) 10(17.5,5) 11(17.5,10) 12(17.5,15)
  silkscreen extent -20.62,-20.7 19.9,20.7, body extent -20,-20.8 20,20.8, height 0.25
FP-BLM15EX331SN1D_0402-MFG [mm]
  rrect25% 0.4x0.5 smd paste+0 mask+0: 1(-0.4,0) 2(0.4,0)
  silkscreen extent -0.53,-0.63 0.52,0.63, body extent -0.7,-0.38 0.7,0.38, height 0.25
FP-C4AKOBU4500A31J_RADIAL-MFG [mm]
  rrect5% 2.15x2.15 hole 1.4 paste-1000 mask+0: 1(-13.75,0.05)
  round 2.15 hole 1.4 paste-1000 mask+0: 2(13.75,0)
  silkscreen extent -16.35,-9.85 16.35,9.85, body extent -16.45,-9.95 16.45,9.95, height 0.25
FP-CL10A105KA8NNNC_0603-IPC_C [mm]
  rrect13% 0.758x0.812 smd paste+0 mask+0: 1(-0.627,0) 2(0.627,0)
  silkscreen extent -1.01,-0.85 1.01,0.85, body extent -1.11,-0.55 1.11,0.55, height 0.25
FP-CSD17318Q2_WSON6-MFG [mm]
  rrect33% 0.45x0.3 smd paste+0 mask+0: 1(-0.975,0.65) 2(-0.975,0) 3(-0.975,-0.65) 4(0.975,-0.65) 5(0.975,0) 6(0.975,0.65)
  rrect33% 0.75x0.3 smd paste-1000 mask+0: 7(0.095,-0.65)
  rrect11% 1x0.95 smd paste-1000 mask+0: 8(0,0.325)
  body extent -1.3,-1.15 1.3,1.15, height 0.25
FP-D6744_PTH_CMC_38MM0-MFG [mm]
  rrect4% 2.7x2.7 hole 1.5 paste-1000 mask+0: 1(5,17.5)
  round 2.7 hole 1.5 paste-1000 mask+0: 2(5,-4.5) 3(-5,-4.5) 4(-5,17.5)
  silkscreen extent -19,-19 19,19.53, body extent -20.09,-20.09 20.09,20.09, height 0.25
FP-F862FY475K310ZV054_RADIAL-MFG [mm]
  rrect6% 1.55x1.55 hole 1 paste-1000 mask+0: 1(-13.75,0)
  round 1.55 hole 1 paste-1000 mask+0: 2(13.75,0)
  silkscreen extent -15.75,-11 15.75,11, body extent -15.85,-11.1 15.85,11.1, height 0.25
FP-GB02SLT12-214_DO-214AA-MFG [mm]
  rrect5% 2.16x2.26 smd paste+0 mask+0: 1(-2.45,0) 2(2.45,0)
  silkscreen extent -4.3,-1.97 2.28,1.97, body extent -3.63,-2.07 3.63,2.07, height 0.25
FP-IsoM5-275-B-L2_RADIAL-MFG [mm]
  rrect6% 1.55x1.55 hole 1 paste-1000 mask+0: 1(-3.75,0)
  round 1.55 hole 1 paste-1000 mask+0: 2(3.75,0)
  silkscreen extent -8.5,-3.15 8.5,3.15, body extent -8.6,-3.25 8.6,3.25, height 0.25
"FP-KG DELLS1.22-JGKH-24_0603-MFG" [mm]
  rrect20% 1.05x0.5 smd paste-1000 mask+0: 1(-0.47,0)
  rrect20% 0.7x0.5 smd paste-1000 mask+0: 2(0.645,0)
  silkscreen extent -1.67,-0.63 0.75,0.63, body extent -1.09,-0.55 1.09,0.55, height 0.25
FP-MH1608-601Y_0603-MFG [mm]
  rrect14% 0.7x0.7 smd paste+0 mask+0: 1(-0.7,0) 2(0.7,0)
  silkscreen extent -0.87,-0.8 0.87,0.8, body extent -1.15,-0.6 1.15,0.6, height 0.25
FP-PTCEL13R600LBE_RADIAL-MFG [mm]
  rrect7% 1.35x1.35 hole 0.85 paste-1000 mask+0: 1(-2.5,0)
  round 1.35 hole 0.85 paste-1000 mask+0: 2(2.5,0)
  silkscreen extent -6.75,-3.5 6.75,3.5, body extent -6.85,-3.6 6.85,3.6, height 0.25
FP-R413F168050T0K_RADIAL-MFG [mm]
  rrect8% 1.3x1.3 hole 0.8 paste-1000 mask+0: 1(-5,0)
  round 1.3 hole 0.8 paste-1000 mask+0: 2(5,0)
  silkscreen extent -6.65,-3.1 6.65,3.1, body extent -6.75,-3.2 6.75,3.2, height 0.25
FP-RMCF0805ZT0R00_0805-MFG [mm]
  rrect11% 0.9x1.3 smd paste+0 mask+0: 1(-1.05,0) 2(1.05,0)
  silkscreen extent -0.23,-0.67 0.23,0.67, body extent -1.6,-0.77 1.6,0.77, height 0.25
FP-SDEM20161T-4R7MS_SMD2-MFG [mm]
  rrect15% 0.65x1.6 smd paste+0 mask+0: 1(-0.675,0) 2(0.675,0)
  silkscreen extent -1.05,-1.22 1.05,1.2, body extent -1.15,-0.95 1.15,0.95, height 0.25
FP-SF-3812F2000T-2_3812-MFG [mm]
  rrect3% 3.25x3.43 smd paste+0 mask+0: 1(-4.675,0) 2(4.675,0)
  silkscreen extent -2.68,-1.65 2.68,1.65, body extent -6.4,-1.82 6.4,1.82, height 0.25
FP-SHF-112-01-L-D-TH_HDR24-MFG [mm]
  rrect9% 1.12x1.12 hole 0.74 paste-1000 mask+0: 1(-6.985,-0.89)
  round 1.12 hole 0.74 paste-1000 mask+0: 2(-6.985,0.38) 3(-5.715,-0.89) 4(-5.715,0.38) 5(-4.445,-0.89) 6(-4.445,0.38) 7(-3.175,-0.89) 8(-3.175,0.38) 9(-1.905,-0.89) 10(-1.905,0.38) 11(-0.635,-0.89) 12(-0.635,0.38) 13(0.635,-0.89) 14(0.635,0.38) 15(1.905,-0.89) 16(1.905,0.38) 17(3.175,-0.89) 18(3.175,0.38) 19(4.445,-0.89) 20(4.445,0.38) 21(5.715,-0.89) 22(5.715,0.38) 23(6.985,-0.89) 24(6.985,0.38)
  silkscreen extent -10.86,-3.46 10.86,2.86, body extent -10.96,-2.96 10.96,2.96, height 0.25
FP-SSM-107-L-SV-BE_HDR7-MFG [mm]
  rrect10% 1.02x1.905 smd paste+0 mask+0: 1(-7.62,-1.603) 2(-5.08,1.603) 3(-2.54,-1.603) 4(0,1.603) 5(2.54,-1.603) 6(5.08,1.603) 7(7.62,-1.603)
  round 1.02 hole 1.02 unplated paste-1000 mask+0: ""(-7.62,0) ""(-5.08,0) ""(-2.54,0) ""(0,0) ""(2.54,0) ""(5.08,0) ""(7.62,0)
  silkscreen extent -9.02,-3.27 9.02,1.34, body extent -9.12,-2.66 9.12,2.66, height 0.25
FP-ZRB18AR61E106ME01L_0603-MFG [mm]
  rrect13% 0.75x0.9 smd paste+0 mask+0: 1(-0.775,0) 2(0.775,0)
  silkscreen extent 0,-0.5 0,0.5, body extent -1.25,-0.6 1.25,0.6, height 0.25
FR_630X1120 [mm] "TH, 2-Leads, Dia 6.3mm, Lead Spacing 2.5mm"
  rect 1.3x1.3 hole 0.8: 1(-2.5,0)
  round 1.3 hole 0.8: 2(2.5,0)
  silkscreen extent -3.45,-3.45 3.45,3.45, body extent -3.37,-3.39 3.4,3.39, height 15.21
Harwin_S2751-46R [mm] "Test Point, SMT"
  rect 2.2x1.4 smd: 1(0,0)
  body extent -1,-0.6 1,0.6, height 1.4
IEC_HighVoltage_Small [mm]
  silkscreen extent -2.72,-2.24 2.72,2.47
IEC_HotSurface_Small [mm]
  silkscreen extent -2.72,-2.36 2.72,2.35
Keystone5000 [mil] "For Keystone 500x miniature loop terminals"
  round 80 hole 40: 1(0,0)
  silkscreen extent -52,-52 52,52, body extent -49,-49 49,49, height 182
Keystone5001 [mil] "For Keystone 500x miniature loop terminals"
  round 80 hole 40: 1(0,0)
  silkscreen extent -52,-52 52,52, body extent -49,-49 49,49, height 182
Keystone5117 [mil] "For Keystone 500x miniature loop terminals"
  round 80 hole 40: 1(0,0)
  silkscreen extent -52,-52 52,52, body extent -49,-49 49,49, height 182
Keystone_5116 [mil] "For Keystone 500x miniature loop terminals"
  round 80 hole 40: 1(0,0)
  silkscreen extent -58,-58 58,58, body extent -50,-49 50,51, height 183
Label_650x200 [mil] "Thermal Transfer Label"
  round 1 on Mech13: 0(0,0)
  silkscreen extent -325,-100 325,100, body extent -325,-100 325,100, height 1
LPG0002A-MFG [mm]
  rrect9% 1.07x1.7 hole 0.75 paste-1000 mask+0: 1(-1.27,0.21)
  rrect100% 1.07x1.7 hole 0.75 paste-1000 mask+0: 2(1.27,0.21)
  round 0.75 hole 0.75 unplated paste-1000 mask+0: ""(0,0.21)
  silkscreen extent -2.62,-0.81 0.36,0.2, body extent -2.15,-0.91 2.15,1.16, height 0.25
MSS1210 [mm] "Coilcraft MSS1210 series"
  rect 3x5.5 smd: 1(-4.75,0) 2(4.75,0)
  silkscreen extent -6.3,-6.3 6.3,6.3, body extent -6.15,-6.15 6.15,6.15, height 10.2
PW0014A_N [mm] "TSOP, 14-Leads, Body 5x4.4mm, Pitch 0.65mm, IPC Medium Density"
  oval 1.4x0.45 smd: 1(-2.95,1.95) 2(-2.95,1.3) 3(-2.95,0.65) 4(-2.95,0) 5(-2.95,-0.65) 6(-2.95,-1.3) 7(-2.95,-1.95) 8(2.95,-1.95) 9(2.95,-1.3) 10(2.95,-0.65) 11(2.95,0) 12(2.95,0.65) 13(2.95,1.3) 14(2.95,1.95)
  silkscreen extent -3.4,-2.55 1.85,2.55, body extent -3.21,-2.5 3.21,2.5, height 1
PW0016A_N [mm] "TSOP, 16-Leads, Body 5x4.4mm, Pitch 0.65mm, IPC Medium Density"
  oval 1.4x0.45 smd: 1(-2.95,2.275) 2(-2.95,1.625) 3(-2.95,0.975) 4(-2.95,0.325) 5(-2.95,-0.325) 6(-2.95,-0.975) 7(-2.95,-1.625) 8(-2.95,-2.275) 9(2.95,-2.275) 10(2.95,-1.625) 11(2.95,-0.975) 12(2.95,-0.325) 13(2.95,0.325) 14(2.95,0.975) 15(2.95,1.625) 16(2.95,2.275)
  silkscreen extent -3.5,-2.55 1.85,2.75, body extent -3.21,-2.5 3.21,2.5, height 1
RQS0052C-C01-MFG [mm]
  rrect9% 1.15x1.1 smd paste+0 mask+0: 1(-5.725,5.2) 16(-5.725,-5.2) 27(5.725,-5.2) 42(5.725,5.2)
  rrect22% 1.15x0.45 smd paste+0 mask+0: 2(-5.725,4.225) 3(-5.725,3.575) 4(-5.725,2.925) 5(-5.725,2.275) 6(-5.725,1.625) 7(-5.725,0.975) 8(-5.725,0.325) 9(-5.725,-0.325) 10(-5.725,-0.975) 11(-5.725,-1.625) 12(-5.725,-2.275) 13(-5.725,-2.925) 14(-5.725,-3.575) 15(-5.725,-4.225) 28(5.725,-4.225) 29(5.725,-3.575) 30(5.725,-2.925) 31(5.725,-2.275) 32(5.725,-1.625) 33(5.725,-0.975) 34(5.725,-0.325) 35(5.725,0.325) 36(5.725,0.975) 37(5.725,1.625) 38(5.725,2.275) 39(5.725,2.925) 40(5.725,3.575) 41(5.725,4.225)
  rrect15% 0.665x1.15 smd paste+0 mask+0: 17(-2.043,-5.725) 52(-2.043,5.725)
  rrect22% 0.45x1.15 smd paste+0 mask+0: 18(-1.285,-5.725) 19(-0.635,-5.725) 20(0.015,-5.725) 21(0.665,-5.725) 22(1.315,-5.725) 23(1.965,-5.725) 24(2.615,-5.725) 25(3.265,-5.725) 26(3.915,-5.725) 43(3.915,5.725) 44(3.265,5.725) 45(2.615,5.725) 46(1.965,5.725) 47(1.315,5.725) 48(0.665,5.725) 49(0.015,5.725) 50(-0.635,5.725) 51(-1.285,5.725)
  silkscreen extent -7.02,-6.05 4.77,6.05, body extent -6,-6 6,6, height 1
SMA [mm] "Molded Diode, 2-Leads, Body 4.3x2.6mm, IPC Medium Density, based on OnSemi component dimensions and land pattern"
  rect 2x2 smd: 1(-2,0) 2(2,0)
  silkscreen extent -3.66,-1.57 2.79,1.57, body extent -2.6,-1.3 2.6,1.3, height 2.42
SMAF [mm] "SMD, 2-Leads, Body 3.8x2.5mm"
  rect 1.24x1.89 smd: 1(-2.04,0) 2(2.04,0)
  silkscreen extent -3.4,-1.3 2.8,1.3, body extent -2.35,-1.25 2.35,1.25, height 1
SMC [mil] "Molded Diode, 2-Leads, Body 6.9x5.8mm, IPC Medium Density, based on OnSemi component dimensions and land patterns"
  rect 110x150 smd: 1(-140.49,0) 2(140.49,0)
  silkscreen extent -221,-123 189,124, body extent -156,-116 156,116, height 91
SOD-123 [mm] "On Semi recommended land pattern"
  rect 0.915x1.22 smd: 1(-1.637,0) 2(1.637,0)
  silkscreen extent -2.74,-1.17 2.03,1.17, body extent -1.93,-0.9 1.93,0.9, height 1.35
SRN3015 [mm] "SMD, 2-Leads, Body 3x3mm"
  rect 1x2.7 smd: 1(-1.1,0) 2(1.1,0)
  silkscreen extent -0.5,-1.7 0.5,1.7
TNPV1206 [mm] "VISHAY"
  rrect11% 0.9x1.7 smd: 1(-1.6,0) 2(1.6,0)
  silkscreen extent -2.4,-1.2 2.4,1.2, body extent -1.67,-0.87 1.67,0.87, height 0.65
UWT_630x770 [mm] "SMD, 2-Leads, Dia 6.3mm"
  rrect6% 3.5x1.6 smd: 1(-2.7,0) 2(2.7,0)
  body extent -3.5,-3.3 3.5,3.3, height 8
WEEE_Minimum [mm] "WEEElie bin"
  silkscreen extent -2.42,-4.38 2.52,2.65
WURTH_61300211121 [mm] "Header, 2.54mm, 2x1, TH"
  rrect50% 1.65x1.65 hole 1.15: 1(-1.27,0)
  round 1.65 hole 1.15: 2(1.27,0)
  body extent -2.54,-1.27 2.54,1.27, height 8.54
Wurth_618009231121 [mm] "Receptacle, D-Sub, 9 Position, R/A, TH"
  rect 1.5x1.5 hole 1: 1(-10.92,5.54)
  round 1.5 hole 1: 2(-10.92,2.77) 3(-10.92,0) 4(-10.92,-2.77) 5(-10.92,-5.54) 6(-8.08,4.155) 7(-8.08,1.385) 8(-8.08,-1.385) 9(-8.08,-4.155)
  round 3.7 hole 3.2: 10(-9.5,12.5) 11(-9.5,-12.5)
  silkscreen extent -12.78,-15.4 -0.53,15.4, body extent -12.5,-15.4 6,15.4, height 12.5

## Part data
C1: library part CMP-0086078-1, "CAP, CERM, 2200 pF, 3000 V,+/- 10%, B, Dia 12.5mm", Cap_Case=12.5x6x16.5mm, Manufacturer=TDK, TempCo=B, Tolerance_%=10%, Value2=3000V, ValueDisplayed=2200pF
C2 C3 C4 C5: library part CMP-0033686-1, "ALH82, Aluminum Electrolytic, 160 uF, 20%, 600 VDC, -40/+105°C", Leakage Current=288uA, Manufacturer=KEMET, Operating Temperature Range="-40°C to +105°C", Tolerance_%=20%, ValueDisplayed=160uF
C6 C10 C16 C25 C29 C43 C44 C47 C50 C62 C91 C125 C127 C185 C186: library part CMP-0006752-5, "CAP, CERM, 0.1 uF, 25 V, +/- 5%, X7R, 0603", Cap_Case=0603, Manufacturer=AVX, Supplier Part Number 1=478-3713-1-ND, TempCo=X7R, Tolerance_%=5%, Value1="0.05 ohm", Value2=25V, ValueDisplayed=0.1uF
C7 C17 C63 C111 C119 C181: library part CMP-0086152-1, "CAP, CERM, 1 µF, 25 V,+/- 10%, X5R, 0603", Cap_Case=0603, Manufacturer="Taiyo Yuden", TempCo=X5R, Tolerance_%=10%, Value2=25V, ValueDisplayed=1µF
C8 C23 C68 C110: library part CMP-0750039-1, "CAP, CERM, 0.01 µF, 50 V,+/- 10%, X7R, 0603", Cap_Case=0603, Manufacturer="Wurth Elektronik", TempCo=X7R, Tolerance_%=10%, Value2=50V, ValueDisplayed=0.01µF
C9 C13 C14 C26 C27 C32 C33 C34 C35 C36 C37 C41 C42 C48 C51 C52 C53 C56 C59 C60 C71 C72 C77 C78 C79 C80 C82 C83 C86 C87 C89 C92 C93 C96 C97 C98 C100 C101 C107 C108 C112 C113 C130 C131 C132 C133 C134 C135 C136 C137 C139 C145 C146 C151 C152 C157 C158 C163 C164 C167 C168 C170 C171 C172 C173 C174 C175 C177 C178 C179 C180 C187 C190 C192 C193 C194 C196 C199 C200 C202 C204 C206 C208 C209 C218 C219 C231 C232 C234 C235 C245 C246 C247 C248 C249 C250 C253 C254 C255 C256: library part CMP-0007442-5, "CAP, CERM, 220 pF, 50 V, +/- 10%, X7R, 0603", Cap_Case=0603, Manufacturer=MuRata, Supplier Part Number 1=490-1483-1-ND, TempCo=X7R, Tolerance_%=10%, Value1=Unknown, Value2=50V, ValueDisplayed=220pF
C11 C24 C49 C57 C69 C94: library part CMP-0750154-1, "CAP, CERM, 10 µF, 25 V,+/- 10%, X7R, AEC-Q200 Grade 1, 1206", Cap_Case=1206, Manufacturer="Taiyo Yuden", TempCo=X7R, Tolerance_%=10%, Value2=25V, ValueDisplayed=10µF
C12 C58: library part CMP-0007389-4, "CAP, CERM, 0.22 uF, 16 V, +/- 10%, X7R, 0603", Cap_Case=0603, Manufacturer=MuRata, Supplier Part Number 1=490-3293-1-ND, TempCo=X7R, Tolerance_%=10%, Value1=Unknown, Value2=16V, ValueDisplayed=0.22uF
C15 C28 C54 C61 C73 C99: library part CMP-0007975-2, "CAP, CERM, 2.2 uF, 25 V, +/- 10%, X7R, AEC-Q200 Grade 1, 0805", Cap_Case=0805, Manufacturer=TDK, Supplier Part Number 1=445-6965-1-ND, TempCo=X7R, Tolerance_%=10%, Value1=Unknown, Value2=25V, ValueDisplayed=2.2uF
C18 C64: library part CMP-0009474-2, "CAP, CERM, 20 uF, 16 V, +/- 20%, X5R, 0704", Cap_Case=0704, Manufacturer=MuRata, TempCo=X5R, Tolerance_%=20%, Value1=Unknown, Value2=16V, ValueDisplayed=20uF
C19 C188: library part CMP-0007507-5, "CAP, CERM, 10 uF, 25 V, +/- 20%, X5R, 0603", Cap_Case=0603, Manufacturer="Taiyo Yuden", TempCo=X5R, Tolerance_%=20%, Value1=Unknown, Value2=25V, ValueDisplayed=10uF
C20 C65 C120 C121 C124 C126: library part CMP-0094458-1, "10µF ±20% 25V Ceramic Capacitor X5R 0603 (1608 Metric)", Digikey Part Number=490-10991-1-ND, Manufacturer="Murata Electronics", Mouser Part Number=81-ZRB18AR61E106ME1L, Operating Temperature Range="-55°C to +85°C", Temperature Characteristic=X5R, Tolerance_%=20%, ValueDisplayed=10uF
C21 C66: library part CMP-0007209-4, "CAP, CERM, 330 pF, 50 V, +/- 5%, C0G/NP0, 0603", Cap_Case=0603, Manufacturer=MuRata, Supplier Part Number 1=490-1439-1-ND, TempCo=C0G/NP0, Tolerance_%=5%, Value1=Unknown, Value2=50V, ValueDisplayed=330pF
C22 C38 C39 C55 C67 C84 C85 C114 C169 C176 C182 C201 C203: library part CMP-0006837-4, "CAP, CERM, 0.1 uF, 50 V, +/- 10%, X7R, 0603", Cap_Case=0603, Manufacturer="Wurth Elektronik", TempCo=X7R, Tolerance_%=10%, Value1=Unknown, Value2=50V, ValueDisplayed=0.1uF
C30 C31 C46 C76 C88 C90 C229: library part CMP-0009326-2, "CAP, CERM, 0.1 uF, 1000 V, +/- 10%, X7R, 1812", Cap_Case=1812, Manufacturer=Kemet, Supplier Part Number 1=399-6523-1-ND, TempCo=X7R, Tolerance_%=10%, Value1=Unknown, Value2=1000V, ValueDisplayed=0.1uF
C40 C238 C239 C240 C251 C252: library part CMP-0081462-1, "CAP, AL, 100 µF, 25 V, +/- 20%, SMD", Cap_Case=6.3x7.7mm, Manufacturer=Nichicon, Supplier Part Number 1=493-2190-1-ND, Tolerance_%=20%, Value2=25V, ValueDisplayed=100µF
C45 C74 C75 C81 C129: library part CMP-0007225-4, "CAP, CERM, 560 pF, 50 V, +/- 5%, C0G/NP0, 0603", Cap_Case=0603, Manufacturer=MuRata, Supplier Part Number 1=490-1445-1-ND, TempCo=C0G/NP0, Tolerance_%=5%, Value1=Unknown, Value2=50V, ValueDisplayed=560pF
C70 C95: library part CMP-0007378-5, "CAP, CERM, 0.1 uF, 16 V, +/- 10%, X7R, 0603", Cap_Case=0603, Manufacturer=MuRata, Supplier Part Number 1=490-1532-1-ND, TempCo=X7R, Tolerance_%=10%, Value1=Unknown, Value2=16V, ValueDisplayed=0.1uF
C102 C106: library part CMP-0042924-1, "6800 pF Film Capacitor 300V 1500V (1.5kV) Polypropylene (PP), Metallized Radial", Digikey Part Number=399-R413F168050T0K-ND, Manufacturer=KEMET, Mouser Part Number=80-R413F168050T0K, Operating Temperature Range="-40°C to +125°C", Tolerance_%=10%, ValueDisplayed=6800pF, Voltage Ac Rating Y=300V
C103 C104: library part CMP-0038396-1, "4.7 µF Film Capacitor 310V 630V Polypropylene (PP), Metallized Radial", Digikey Part Number=399-F862FY475K310ZV054-ND, Manufacturer=KEMET, Mouser Part Number=80-F862FY475K31ZV054, Operating Temperature Range="-40°C to +110°C", Tolerance_%=10%, ValueDisplayed=4.7uF, Voltage Ac Rating X=310V
C105 C109 C115: library part CMP-0007470-5, "CAP, CERM, 0.1 uF, 100 V, +/- 10%, X7R, 0603", Cap_Case=0603, Manufacturer=MuRata, Supplier Part Number 1=490-6439-1-ND, TempCo=X7R, Tolerance_%=10%, Value1=Unknown, Value2=100V, ValueDisplayed=0.1uF
C116: library part CMP-0010555-2, "CAP, AL, 10 uF, 35 V, +/- 20%, TH", Cap_Case=5x11, Manufacturer=Nichicon, Supplier Part Number 1=UVR1V100MDD1TA-ND, Tolerance_%=20%, Value1=Unknown, Value2=35V, ValueDisplayed=10uF
C117: library part CMP-0006775-4, "CAP, CERM, 22 pF, 50 V, +/- 5%, C0G/NP0, 0603", Cap_Case=0603, Manufacturer=AVX, Supplier Part Number 1=478-1167-1-ND, TempCo=C0G/NP0, Tolerance_%=5%, Value1="0.259 ohm", Value2=50V, ValueDisplayed=22pF
C118: library part CMP-0010348-1, "CAP, AL, 150 uF, 25 V, +/- 20%, TH", Cap_Case=6.3x11.2mm, Manufacturer=Panasonic, Supplier Part Number 1=P15352CT-ND, Tolerance_%=20%, Value1=Unknown, Value2=25V, ValueDisplayed=150uF
C122 C123: library part CMP-0064932-4, "CAP, CERM, 1 uF, 10 V,+/- 10%, X7R, 0603", Cap_Case=0603, Manufacturer="Wurth Elektronik", Supplier Part Number 1=732-7945-1-ND, TempCo=X7R, Tolerance_%=10%, Value1=Unknown, Value2=10V, ValueDisplayed=1uF
C128 C138 C140 C141 C142 C161 C165 C230: library part CMP-0006979-5, "CAP, CERM, 0.1 uF, 25 V, +/- 10%, X7R, 0603", Cap_Case=0603, Manufacturer=Kemet, Supplier Part Number 1=399-5345-1-ND, TempCo=X7R, Tolerance_%=10%, Value1=Unknown, Value2=25V, ValueDisplayed=0.1uF
C143 C148 C155 C160: library part CMP-0007194-4, "CAP, CERM, 200 pF, 50 V, +/- 5%, C0G/NP0, 0603", Cap_Case=0603, Manufacturer=MuRata, Supplier Part Number 1=490-1434-1-ND, TempCo=C0G/NP0, Tolerance_%=5%, Value1=Unknown, Value2=50V, ValueDisplayed=200pF
C150 C154 C156 C159 C162 C166: library part CMP-0007195-4, "CAP, CERM, 2000 pF, 50 V, +/- 5%, C0G/NP0, 0603", Cap_Case=0603, Manufacturer=MuRata, Supplier Part Number 1=490-1458-1-ND, TempCo=C0G/NP0, Tolerance_%=5%, Value1=Unknown, Value2=50V, ValueDisplayed=2000pF
C189 C198 C210 C211 C214 C223 C226: library part CMP-0094926-1, "Cap Ceramic 1uF 25V X5R ±10% Pad SMD 0603 +85°C T/R", Manufacturer=Samsung, Operating Temperature Range="-55°C to +85°C", TempCo=0.15, Temperature Characteristic=X5R, Tolerance_%=10%, ValueDisplayed=1uF
C191 C207 C213 C215 C225 C228: library part CMP-0008310-2, "CAP, CERM, 10 uF, 35 V, +/- 10%, X5R, 0805", Cap_Case=0805, Manufacturer=MuRata, Supplier Part Number 1=490-10514-1-ND, TempCo=X5R, Tolerance_%=10%, Value1=Unknown, Value2=35V, ValueDisplayed=10uF
C195 C197 C205 C216 C222 C224: library part CMP-0085850-1, "CAP, CERM, 0.1 µF, 16 V,+/- 10%, X7R, 0402", Cap_Case=0402, Manufacturer=Walsin, TempCo=X7R, Tolerance_%=10%, Value2=16V, ValueDisplayed=0.1µF
C212 C227: library part CMP-0085842-1, "CAP, CERM, 0.01 µF, 50 V,+/- 10%, X7R, 0402", Cap_Case=0402, Manufacturer=Walsin, TempCo=X7R, Tolerance_%=10%, Value2=50V, ValueDisplayed=0.01µF
C217 C221 C233 C237: library part CMP-0007220-4, "CAP, CERM, 47 pF, 50 V, +/- 5%, C0G/NP0, 0603", Cap_Case=0603, Manufacturer=MuRata, Supplier Part Number 1=490-1419-1-ND, TempCo=C0G/NP0, Tolerance_%=5%, Value1=Unknown, Value2=50V, ValueDisplayed=47pF
C220 C236: library part CMP-0006987-4, "CAP, CERM, 4700 pF, 50 V, +/- 10%, X7R, 0603", Cap_Case=0603, Manufacturer=Kemet, Supplier Part Number 1=399-5337-1-ND, TempCo=X7R, Tolerance_%=10%, Value1=Unknown, Value2=50V, ValueDisplayed=4700pF
C241 C242: library part CMP-0037193-1, "5 µF Film Capacitor 900V Polypropylene (PP), Metallized Radial", Digikey Part Number=399-C4AKOBU4500A31J-ND, Manufacturer=Kemet, Mouser Part Number=80-C4AKOBU4500A31J, Operating Temperature Range="-55°C to +135°C", Tolerance_%=5%, ValueDisplayed=5uF
C243 C244: library part CMP-0009613-2, "CAP, CERM, 2200 pF, 300 V, +/- 20%, E, TH, 2- Leads, Body 9x7mm, Pin Spacing 7.5mm", Cap_Case=9x7x9mm, Manufacturer=MuRata, Supplier Part Number 1=DE6E3KJ222MN3A-ND, TempCo=E, Tolerance_%=20%, Value1=Unknown, Value2=300V, ValueDisplayed=2200pF
D1 D7: library part CMP-0095009-1, "Diode Silicon Carbide Schottky 1200 V 2A (DC) Surface Mount DO-214AA", Digikey Part Number=1242-1170-1-ND, Forward Current=2A, Manufacturer="GeneSiC Semiconductor", Max Surge Forward Current=20A, Mouser Part Number=905-GB02SLT12-214, Operating Temperature Range="-55°C to +175°C", Peak Reverse Current=1uA, ValueDisplayed=122pF
D2 D8 D19: library part CMP-0005769-4, "Diode, Zener, 16 V, 500 mW, AEC-Q101, SOD-123", Manufacturer="Diodes Inc.", Power_W=500mW, Value1=0.5W
D4 D10 D16 D17 D18 D23 D24 D25 D26 D27 D28: library part CMP-0093310-1, "Standard LEDs - SMD Green TOPLED E 1608", Color=Green, Forward Current=2mA, Manufacturer="Osram Opto", Mouser Part Number=720-KGDELLS122A4849, Operating Temperature Range="-40°C to +110°C"
D13: library part CMP-0028389-2, "Diode, Schottky, 60 V, 1 A, SMA", Manufacturer="Diodes Inc.", Value1=1A, Value2=0.7V
D14: library part CMP-0029001-2, "Diode, Ultrafast, 100 V, 0.15 A, SOD-123", Manufacturer="Diodes Inc.", Value1=0.15A, Value2=1.25V
D15: library part CMP-0029162-2, "Diode, Ultrafast, 600 V, 1 A, AEC-Q101, SMAF", Manufacturer="Fairchild Semiconductor", Value1=1A, Value2=1.7V
D20: library part CMP-0076883-2, "Diode, Switching, 800 V, 3 A, SMC", Manufacturer=Vishay-Semiconductor, Value1=3A, Value2=1.3V
F1 F2: library part CMP-0042962-1, "20 A 250 V AC 80 V DC Fuse Board Mount (Cartridge Style Excluded) Surface Mount 2-SMD, Square End Block", Digikey Part Number=SF-3812F2000T-2CT-ND, Fuse Current=20A, Fuse Interrupt Dc Current=300A, Manufacturer=Bourns, Mouser Part Number=652-SF-3812F2000T-2, Operating Temperature Range="-55°C to +125°C"
FB1 FB2 FB3 FB4 FB5 FB6 FB7 FB8 FB9 FB11 FB12 FB13 FB14 FB15: library part CMP-0037505-1, "600 Ohms @ 100 MHz 1 Power, Signal Line Ferrite Bead 0603 (1608 Metric) 1A 200mOhm", Digikey Part Number=MH1608-601YCT-ND, Impedance At Frequency="600Ω @ 100MHz", Manufacturer=Bourns, Mouser Part Number=652-MH1608-601Y, Operating Temperature Range="-55°C to +125°C", Test Frequency=100MHz, Tolerance_%=25%
FB18 FB23: library part CMP-0041881-1, "Chip Ferrite Bead, 0402, 330Ω @ 100MHz, 0.205Ω, 25%, 1.1A", Impedance At Frequency="330Ω @ 100MHz", Manufacturer=Murata, Operating Temperature Range="-55°C to +125°C", Test Frequency=100MHz, Tolerance_%=25%
FID1 FID2 FID3 FID4 FID5 FID6: library part CMP-0077181-1, "Fiducial mark.  There is nothing to buy or mount.", Manufacturer=N/A
J1 J2 J3: library part CMP-0094328-1, "3 Position Terminal Block Header, Male Pins, Shrouded (4 Side) 0.200\" (5.08mm) Vertical - Through Hole", Current_A=15A, Digikey Part Number=A98423-ND, Manufacturer="TE Connectivity", Mouser Part Number=571-796636-3, Operating Temperature Range="-40°C to +105°C", Voltage_V=300V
